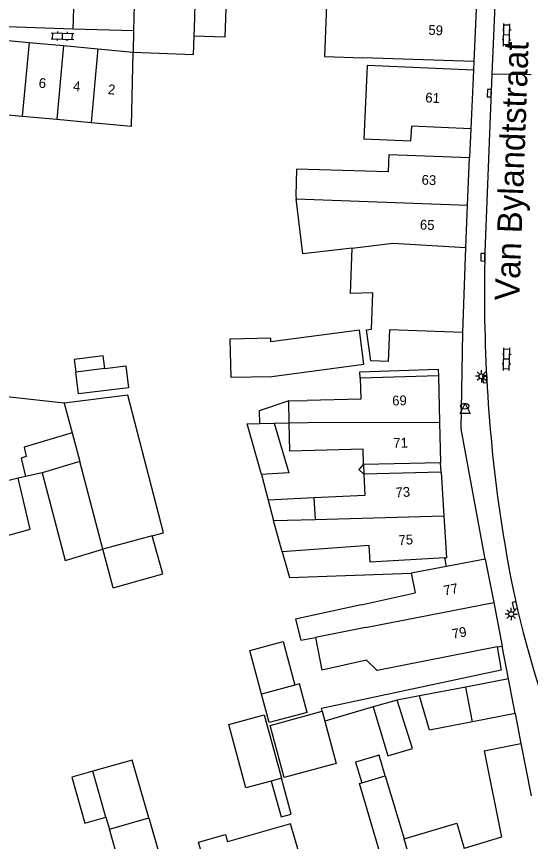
# Model space of a CAD drawing. Extents: x 132998 to 136004, y 396998 to 398512.
# Drawn here: x 133102.8 to 133155.2, y 397751.1 to 397835.1 of the extents above; entities that cross this region are included whole.
import ezdxf

# ---------------------------------------------------------------- set-up
doc = ezdxf.new("R2010")
doc.units = 0
for name, color, linetype in [('gg-afsc-erfafscheiding', 7, 'Continuous'), ('gg-afsc-muur', 7, 'Continuous'), ('gg-anno-huisnummerreeks BGT', 7, 'Continuous'), ('gg-anno-openbare ruimte label', 7, 'Continuous'), ('gg-bbg-bijgebouw', 7, 'Continuous'), ('gg-bbg-gedigitaliseerde bebouwing', 7, 'Continuous'), ('gg-bbg-gedigitaliseerde bebouwing onder overbouw', 7, 'Continuous'), ('gg-bbg-gedigitaliseerde bijgebouw', 7, 'Continuous'), ('gg-bbg-gedigitaliseerde overbouw', 7, 'Continuous'), ('gg-bbg-hoofdgebouw', 7, 'Continuous'), ('gg-bbg-luifel en loopbrug', 7, 'Continuous'), ('gg-bbg-pand overbouw', 7, 'Continuous'), ('gg-bbg-tussenscheiding', 7, 'Continuous'), ('gg-knt-verharding', 7, 'Continuous'), ('gt-grn-vlakafsluiter', 7, 'Continuous'), ('gt-grn-weggrens', 7, 'Continuous'), ('gt-symb-brandkraan', 7, 'Continuous'), ('gt-symb-klinker verharding', 7, 'Continuous'), ('gt-symb-kolk', 7, 'Continuous'), ('gt-symb-lichtmast', 7, 'Continuous'), ('gt-symb-waterafsluiter', 7, 'Continuous')]:
    doc.layers.add(name, color=color, linetype=linetype)

# ---------------------------------------------------------------- blocks, each defined once
blk = doc.blocks.new('gt0-KL1')
at = {"layer": 'gt-symb-klinker verharding'}
for p, q in [((-1.15, 0.3), (1.15, 0.3)), ((-1, -0.3), (-1, 0.3)), ((-0.5, 0.3), (-0.5, 0.45)), ((0, -0.3), (0, 0.3)), ((0.5, 0.3), (0.5, 0.45)), ((1, -0.3), (1, 0.3)), ((-1.15, -0.3), (1.15, -0.3)), ((-0.5, -0.45), (-0.5, -0.3)), ((0.5, -0.45), (0.5, -0.3))]:
    blk.add_line(p, q, dxfattribs=at)
blk = doc.blocks.new('gt0-KOLK')
at = {"layer": 'gt-symb-kolk'}
blk.add_lwpolyline([(0, 0), (0.375, 0), (0.375, 0.4), (-0.375, 0.4), (-0.375, 0), (0, 0)], dxfattribs=at)
blk = doc.blocks.new('gt0-BR')
at = {"layer": 'gt-symb-brandkraan'}
for centre, radius, start, end in [((-0.244, 0), 0.206, 107.56694, 252.43307), ((0.599, -2.664), 3, 106.89205, 107.56694), ((0, -0.691), 0.938, 73.10799, 106.89205), ((-0.599, -2.664), 3, 72.43309, 73.10799), ((0.244, 0), 0.206, 287.56695, 72.43309), ((0.599, 2.664), 3, 252.43307, 253.10797), ((0, 0.691), 0.938, 253.10797, 286.89206), ((-0.599, 2.664), 3, 286.89206, 287.56695)]:
    blk.add_arc(centre, radius, start, end, dxfattribs=at)
blk = doc.blocks.new('gt0-WAFSL')
at = {"layer": 'gt-symb-waterafsluiter'}
for p, q in [((-0.5, -0.333), (0, 0.667)), ((0, 0.667), (0.5, -0.333)), ((0.5, -0.333), (-0.5, -0.333))]:
    blk.add_line(p, q, dxfattribs=at)
blk = doc.blocks.new('gt0-LMAST')
at = {"layer": 'gt-symb-lichtmast'}
for p, q in [((-0.182, 0.173), (-0.447, 0.438)), ((-0.005, 0.246), (-0.005, 0.621)), ((0.172, 0.173), (0.437, 0.438)), ((-0.255, -0.004), (-0.63, -0.004)), ((-0.182, -0.181), (-0.447, -0.446)), ((-0.005, -0.254), (-0.005, -0.629)), ((0.437, -0.446), (0.172, -0.181)), ((0.245, -0.004), (0.62, -0.004))]:
    blk.add_line(p, q, dxfattribs=at)
blk.add_circle((-0.005, -0.004), 0.25, dxfattribs=at)

msp = doc.modelspace()

# ---------------------------------------------------------------- linework, layer by layer
at = {"layer": 'gg-afsc-erfafscheiding'}
for p, q in [((133107.668, 397795.753), (133097.154, 397796.925)), ((133103.727, 397788.282), (133102.986, 397788.115)), ((133127.771, 397788.481), (133128.458, 397785.862)), ((133146.616, 397779.126), (133146.45, 397780)), ((133143.881, 397765.93), (133141.595, 397765.501)), ((133139.159, 397764.824), (133134.229, 397763.347)), ((133153.628, 397764.127), (133154.205, 397761.088))]:
    msp.add_line(p, q, dxfattribs=at)
for points in [[(133138.148, 397789.54), (133137.674, 397789.01), (133138.199, 397788.531)], [(133129.887, 397780.603), (133130.607, 397777.993), (133143.022, 397778.448)], [(133151.78, 397770.916), (133152.196, 397768.564), (133133.876, 397764.653)], [(133123.467, 397743.621), (133121.351, 397751.051), (133124.101, 397751.834), (133124.313, 397751.087)]]:
    msp.add_lwpolyline(points, dxfattribs=at)
at = {"layer": 'gg-afsc-muur'}
msp.add_lwpolyline([(133150.561, 397779.87), (133148.13, 397793.14), (133148.28, 397802.95)], dxfattribs=at)
at = {"layer": 'gg-bbg-bijgebouw'}
for p, q in [((133114.741, 397833.69), (133114.692, 397831.514)), ((133099.924, 397832.871), (133104.082, 397832.489)), ((133104.082, 397832.489), (133107.583, 397832.167)), ((133107.583, 397832.167), (133111.078, 397831.846)), ((133111.078, 397831.846), (133114.692, 397831.514)), ((133114.154, 397796.561), (133107.668, 397795.753)), ((133107.668, 397795.753), (133108.478, 397792.734)), ((133108.478, 397792.734), (133109.265, 397789.803)), ((133109.265, 397789.803), (133105.422, 397788.663)), ((133102.986, 397788.115), (133094.622, 397786.082)), ((133153.628, 397764.127), (133152.943, 397767.662))]:
    msp.add_line(p, q, dxfattribs=at)
msp.add_lwpolyline([(133115.139, 397843.656), (133114.86, 397838.91), (133114.741, 397833.69)], dxfattribs=at)
at = {"layer": 'gg-bbg-gedigitaliseerde bebouwing'}
for p, q in [((133149.416, 397830.544), (133138.083, 397830.915)), ((133145.8, 397798.55), (133137.822, 397798.282)), ((133130.554, 397795.99), (133132.424, 397796.03)), ((133133.093, 397786.097), (133133.223, 397783.917)), ((133129.004, 397783.804), (133133.223, 397783.917)), ((133129.887, 397780.603), (133129.004, 397783.804)), ((133138.756, 397781.239), (133129.887, 397780.603)), ((133146.45, 397780), (133146.62, 397780.01)), ((133146.616, 397779.126), (133143.022, 397778.448)), ((133143.022, 397778.448), (133143.416, 397776.425)), ((133137.927, 397775.213), (133143.416, 397776.425)), ((133133.284, 397771.899), (133133.933, 397768.573)), ((133151.78, 397770.916), (133139.562, 397768.518)), ((133150.458, 397760.327), (133152.215, 397751.542)), ((133140.379, 397757.793), (133142.297, 397751.375)), ((133112.27, 397752.378), (133116.285, 397753.528)), ((133116.285, 397753.528), (133117.769, 397748.348)), ((133152.215, 397751.542), (133148.425, 397750.408))]:
    msp.add_line(p, q, dxfattribs=at)
for points in [[(133138.376, 397837.061), (133134.417, 397837.216), (133134.176, 397831.068), (133138.083, 397830.915)], [(133149.374, 397829.65), (133138.526, 397830.141), (133138.187, 397822.633)], [(133140.725, 397819.318), (133140.79, 397821.08), (133148.95, 397820.77)], [(133140.725, 397819.318), (133131.341, 397819.571), (133131.268, 397816.898), (133131.308, 397816.57)], [(133137.007, 397811.549), (133131.992, 397810.942), (133131.308, 397816.57)], [(133148.28, 397802.95), (133140.807, 397803.234), (133140.685, 397799.997), (133138.895, 397800.064), (133138.48, 397803.217), (133138.975, 397803.288), (133139.114, 397806.977), (133136.832, 397806.903), (133137.007, 397811.549)], [(133137.822, 397798.282), (133137.903, 397796.148), (133132.424, 397796.03)], [(133138.148, 397789.54), (133138.113, 397791.05), (133130.669, 397790.877), (133130.602, 397793.753)], [(133138.199, 397788.531), (133138.309, 397786.361), (133133.093, 397786.097)], [(133146.45, 397780), (133138.858, 397779.544), (133138.756, 397781.239)], [(133137.927, 397775.213), (133131.244, 397773.737), (133131.783, 397771.606), (133133.284, 397771.899)], [(133139.562, 397768.518), (133138.478, 397769.577), (133133.933, 397768.573)], [(133137.333, 397749.233), (133139.842, 397749.984), (133137.74, 397757.002), (133137.984, 397757.075)], [(133142.297, 397751.375), (133147.656, 397752.979), (133148.425, 397750.408)], [(133115.078, 397745.696), (133114.58, 397747.434), (133113.754, 397747.197), (133112.27, 397752.378)]]:
    msp.add_lwpolyline(points, dxfattribs=at)
at = {"layer": 'gg-bbg-gedigitaliseerde bebouwing onder overbouw'}
for p, q in [((133138.148, 397789.54), (133146.02, 397789.72)), ((133146.082, 397788.711), (133138.199, 397788.531))]:
    msp.add_line(p, q, dxfattribs=at)
at = {"layer": 'gg-bbg-gedigitaliseerde bijgebouw'}
for p, q in [((133099.718, 397825.326), (133103.39, 397824.989)), ((133103.39, 397824.989), (133106.904, 397824.666)), ((133106.904, 397824.666), (133110.399, 397824.345)), ((133111.789, 397799.268), (133108.847, 397798.902)), ((133129.076, 397793.72), (133130.602, 397793.753)), ((133131.162, 397767.028), (133127.784, 397766.114)), ((133152.943, 397767.662), (133148.576, 397766.827)), ((133149.264, 397763.281), (133148.576, 397766.827)), ((133141.595, 397765.501), (133139.159, 397764.824)), ((133133.954, 397764.364), (133134.229, 397763.347)), ((133153.628, 397764.127), (133149.264, 397763.281)), ((133129.79, 397757.541), (133128.77, 397757.265))]:
    msp.add_line(p, q, dxfattribs=at)
for points in [[(133120.904, 397833.127), (133120.979, 397834.979), (133121.054, 397838.009)], [(133114.692, 397831.514), (133120.828, 397831.265), (133120.904, 397833.127)], [(133110.399, 397824.345), (133114.525, 397823.965), (133114.692, 397831.514)], [(133128.811, 397798.472), (133138.205, 397799.707), (133137.749, 397803.177), (133128.734, 397801.993), (133128.726, 397802.371), (133124.55, 397802.281), (133124.635, 397798.381), (133128.811, 397798.472)], [(133111.789, 397799.268), (133113.954, 397799.538), (133114.23, 397797.324), (133109.122, 397796.688), (133108.847, 397798.902)], [(133116.629, 397782.234), (133117.775, 397782.543), (133114.154, 397796.561)], [(133130.554, 397795.99), (133127.521, 397794.964), (133127.549, 397793.687)], [(133127.771, 397788.481), (133126.322, 397793.66), (133127.549, 397793.687)], [(133129.076, 397793.72), (133130.559, 397788.662), (133127.771, 397788.481)], [(133096.156, 397780.66), (133104.192, 397782.933), (133102.986, 397788.115)], [(133105.422, 397788.663), (133107.761, 397779.715), (133111.6, 397780.878)], [(133112.666, 397776.947), (133117.72, 397778.377), (133116.629, 397782.234)], [(133112.666, 397776.947), (133111.926, 397779.633), (133111.6, 397780.878)], [(133127.784, 397766.114), (133126.584, 397770.555), (133129.962, 397771.468), (133131.162, 397767.028)], [(133139.159, 397764.824), (133140.657, 397759.822), (133143.145, 397760.567), (133141.595, 397765.501)], [(133134.229, 397763.347), (133135.389, 397759.054), (133130.08, 397757.619), (133128.645, 397762.929), (133133.954, 397764.364)], [(133128.77, 397757.265), (133126.175, 397756.564), (133124.432, 397763.015), (133128.047, 397763.992), (133129.79, 397757.541)], [(133140.379, 397757.793), (133139.747, 397759.9), (133137.353, 397759.183), (133137.984, 397757.075)]]:
    msp.add_lwpolyline(points, dxfattribs=at)
at = {"layer": 'gg-bbg-gedigitaliseerde overbouw'}
msp.add_line((133138.148, 397789.54), (133138.199, 397788.531), dxfattribs=at)
at = {"layer": 'gg-bbg-hoofdgebouw'}
for p, q in [((133149.684, 397836.618), (133149.416, 397830.544)), ((133149.374, 397829.65), (133149.104, 397823.679)), ((133149.104, 397823.679), (133143.048, 397823.953)), ((133148.767, 397815.914), (133148.95, 397820.77)), ((133148.605, 397811.605), (133148.767, 397815.914)), ((133148.28, 397802.95), (133148.605, 397811.605)), ((133145.8, 397798.55), (133145.918, 397793.805)), ((133145.918, 397793.805), (133146.02, 397789.72)), ((133146.082, 397788.711), (133146.357, 397784.268)), ((133146.357, 397784.268), (133146.62, 397780.01)), ((133150.561, 397779.87), (133146.616, 397779.126)), ((133150.561, 397779.87), (133151.426, 397775.44)), ((133151.426, 397775.44), (133152.29, 397771.01)), ((133151.78, 397770.916), (133152.29, 397771.01)), ((133150.458, 397760.327), (133154.205, 397761.088)), ((133154.205, 397761.088), (133155.244, 397755.748))]:
    msp.add_line(p, q, dxfattribs=at)
msp.add_lwpolyline([(133143.048, 397823.953), (133142.967, 397822.424), (133138.187, 397822.633)], dxfattribs=at)
at = {"layer": 'gg-bbg-luifel en loopbrug'}
for p, q in [((133105.422, 397788.663), (133103.727, 397788.282)), ((133133.093, 397786.097), (133128.458, 397785.862)), ((133128.458, 397785.862), (133129.004, 397783.804)), ((133148.576, 397766.827), (133143.881, 397765.93)), ((133111.923, 397753.588), (133110.586, 397758.256)), ((133111.923, 397753.588), (133112.27, 397752.378))]:
    msp.add_line(p, q, dxfattribs=at)
for points in [[(133121.054, 397838.009), (133124.19, 397837.882), (133124.04, 397833.03), (133120.904, 397833.127)], [(133111.789, 397799.268), (133111.626, 397800.572), (133108.684, 397800.205), (133108.847, 397798.902)], [(133137.822, 397798.282), (133137.797, 397798.94), (133145.784, 397799.208), (133145.8, 397798.55)], [(133108.478, 397792.734), (133103.573, 397791.279), (133103.799, 397790.31), (133103.29, 397790.16), (133103.727, 397788.282)], [(133132.415, 397764.258), (133131.632, 397767.154), (133131.162, 397767.028)], [(133132.415, 397764.258), (133128.566, 397763.218), (133127.784, 397766.114)], [(133149.264, 397763.281), (133144.899, 397762.435), (133143.881, 397765.93)], [(133116.285, 397753.528), (133114.601, 397759.406), (133110.586, 397758.256)], [(133110.586, 397758.256), (133108.443, 397757.642), (133109.78, 397752.975), (133111.923, 397753.588)], [(133128.77, 397757.265), (133129.758, 397753.611), (133130.777, 397753.886), (133129.79, 397757.541)], [(133132.266, 397747.716), (133130.734, 397752.919), (133124.313, 397751.087)]]:
    msp.add_lwpolyline(points, dxfattribs=at)
at = {"layer": 'gg-bbg-pand overbouw'}
msp.add_line((133146.082, 397788.711), (133146.02, 397789.72), dxfattribs=at)
at = {"layer": 'gg-bbg-tussenscheiding'}
for p, q in [((133104.082, 397832.489), (133103.39, 397824.989)), ((133107.583, 397832.167), (133106.904, 397824.666)), ((133111.078, 397831.846), (133110.399, 397824.345)), ((133131.308, 397816.57), (133148.767, 397815.914)), ((133130.602, 397793.753), (133130.554, 397795.99)), ((133127.549, 397793.687), (133129.076, 397793.72)), ((133111.6, 397780.878), (133109.265, 397789.803)), ((133133.223, 397783.917), (133146.357, 397784.268)), ((133116.629, 397782.234), (133111.6, 397780.878)), ((133138.379, 397772.893), (133151.426, 397775.44)), ((133138.379, 397772.893), (133133.284, 397771.899)), ((133137.984, 397757.075), (133140.379, 397757.793)), ((133143.335, 397747.904), (133142.297, 397751.375))]:
    msp.add_line(p, q, dxfattribs=at)
for points in [[(133137.007, 397811.549), (133141.139, 397812.049), (133148.605, 397811.605)], [(133130.602, 397793.753), (133132.456, 397793.793), (133145.918, 397793.805)]]:
    msp.add_lwpolyline(points, dxfattribs=at)
at = {"layer": 'gg-knt-verharding'}
for p, q in [((133151.856, 397844.15), (133151.252, 397829.273)), ((133108.588, 397833.885), (133108.738, 397839.587)), ((133099.965, 397834.158), (133108.588, 397833.885)), ((133108.588, 397833.885), (133114.741, 397833.69)), ((133149.416, 397830.544), (133149.374, 397829.65)), ((133151.252, 397829.273), (133150.62, 397813.72)), ((133155.25, 397829.19), (133151.252, 397829.273)), ((133149.104, 397823.679), (133148.95, 397820.77)), ((133151.81, 397786.195), (133152.408, 397782.325))]:
    msp.add_line(p, q, dxfattribs=at)
for centre, radius, start, end in [((133315.062, 397807.041), 164.578, 177.67421, 187.27689), ((133251.162, 397797.315), 99.885, 188.63109, 198.98824)]:
    msp.add_arc(centre, radius, start, end, dxfattribs=at)
at = {"layer": 'gt-grn-vlakafsluiter'}
msp.add_line((133133.954, 397764.364), (133133.876, 397764.653), dxfattribs=at)
at = {"layer": 'gt-grn-weggrens'}
msp.add_line((133152.943, 397767.662), (133152.29, 397771.01), dxfattribs=at)

# ---------------------------------------------------------------- block references
at = {"layer": 'gt-symb-brandkraan'}
msp.add_blockref('gt0-BR', (133148.477, 397795.432), dxfattribs=at)
at = {"layer": 'gt-symb-klinker verharding'}
for p, rotation in [((133152.745, 397833.243), 88.39613722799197), ((133107.492, 397833.125), -2.0638197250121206), ((133152.745, 397800.231), 88.39613722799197)]:
    msp.add_blockref('gt0-KL1', p, dxfattribs=dict(at, rotation=rotation))
at = {"layer": 'gt-symb-kolk'}
for p, rotation in [((133151.172, 397827.312), 87.59258615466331), ((133150.522, 397810.603), 88.96878732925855), ((133150.72, 397798.213), 93.03686894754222), ((133153.775, 397775.189), 103.17492660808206)]:
    msp.add_blockref('gt0-KOLK', p, dxfattribs=dict(at, rotation=rotation))
at = {"layer": 'gt-symb-lichtmast'}
for p in [(133150.188, 397798.492), (133153.22, 397774.268)]:
    msp.add_blockref('gt0-LMAST', p, dxfattribs=at)
at = {"layer": 'gt-symb-waterafsluiter'}
msp.add_blockref('gt0-WAFSL', (133148.522, 397795.033), dxfattribs=at)

# ---------------------------------------------------------------- texts
at = {"layer": 'gg-anno-huisnummerreeks BGT'}
for s, rotation, p in [('59', 357.5, (133144.755, 397833.273)), ('6', 354.7, (133105.033, 397827.883)), ('4', 354.8, (133108.532, 397827.56)), ('2', 354.8, (133112.086, 397827.234)), ('61', 357.4, (133144.444, 397826.381)), ('63', 357.8, (133144.066, 397818.006)), ('65', 357.8, (133143.894, 397813.439)), ('69', 1.4, (133141.097, 397795.505)), ('71', 1.4, (133141.204, 397791.197)), ('73', 3.6, (133141.455, 397786.145)), ('75', 3.6, (133141.755, 397781.291)), ('77', 11.1, (133146.42, 397776.155)), ('79', 11, (133147.281, 397771.732))]:
    msp.add_text(s, height=1, rotation=rotation, dxfattribs=at).set_placement(p)
at = {"layer": 'gg-anno-openbare ruimte label'}
msp.add_text('Van Bylandtstraat', height=2.5, rotation=87.9, dxfattribs=at).set_placement((133154.024, 397806.155))

doc.saveas('drawing.dxf')
